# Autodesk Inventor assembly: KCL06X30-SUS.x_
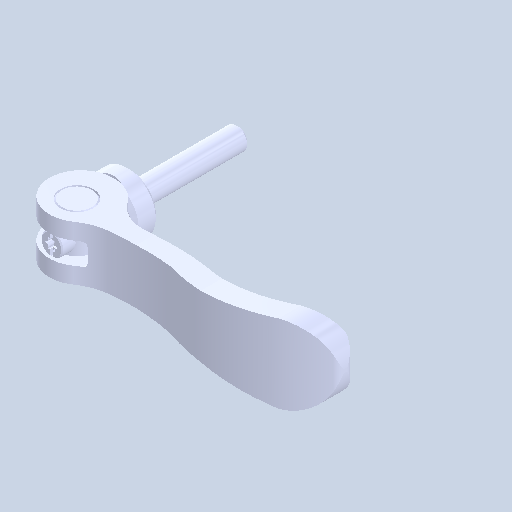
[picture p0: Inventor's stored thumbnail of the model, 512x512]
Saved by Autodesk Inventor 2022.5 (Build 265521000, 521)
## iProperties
Created: 2024-08
Part Number: KCL06X30-SUS.x_
Document SubType Name: Assembly
Designer: ImaoCorp
Author: ImaoCorp
Sending System: SOLIDWORKS 2022-2022290
MC: AMD64
MC_MODEL: Intel64 Family 6 Model 60 Stepping 3, GenuineIntel
OS: Windows_NT
FRU: Parasolid Version 33.1, build 260,  4-25-2022
FORMAT: text
GUISE: transmit
KEY: FILEKCL06X30-SUS.x_t
DATE: Thu Aug 29 10:49:50 2024
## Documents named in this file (5)
- Y:\5.更新分\2024年対応\1001_KCL\データ\kcl06x30-sus\KCL06X30-SUS.x_.iam
- Y:\5.更新分\2024年対応\1001_KCL\データ\kcl06x30-sus\KCL06X30-SUS_01.ipt
- Y:\5.更新分\2024年対応\1001_KCL\データ\kcl06x30-sus\KCL06X30-SUS_02.ipt
- Y:\5.更新分\2024年対応\1001_KCL\データ\kcl06x30-sus\KCL06X30-SUS_03.ipt
- Y:\5.更新分\2024年対応\1001_KCL\データ\kcl06x30-sus\KCL06X30-SUS_04.ipt
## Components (4 placed, 4 different names)
1. KCL06X30-SUS_01
2. KCL06X30-SUS_02
3. KCL06X30-SUS_03
4. KCL06X30-SUS_04
